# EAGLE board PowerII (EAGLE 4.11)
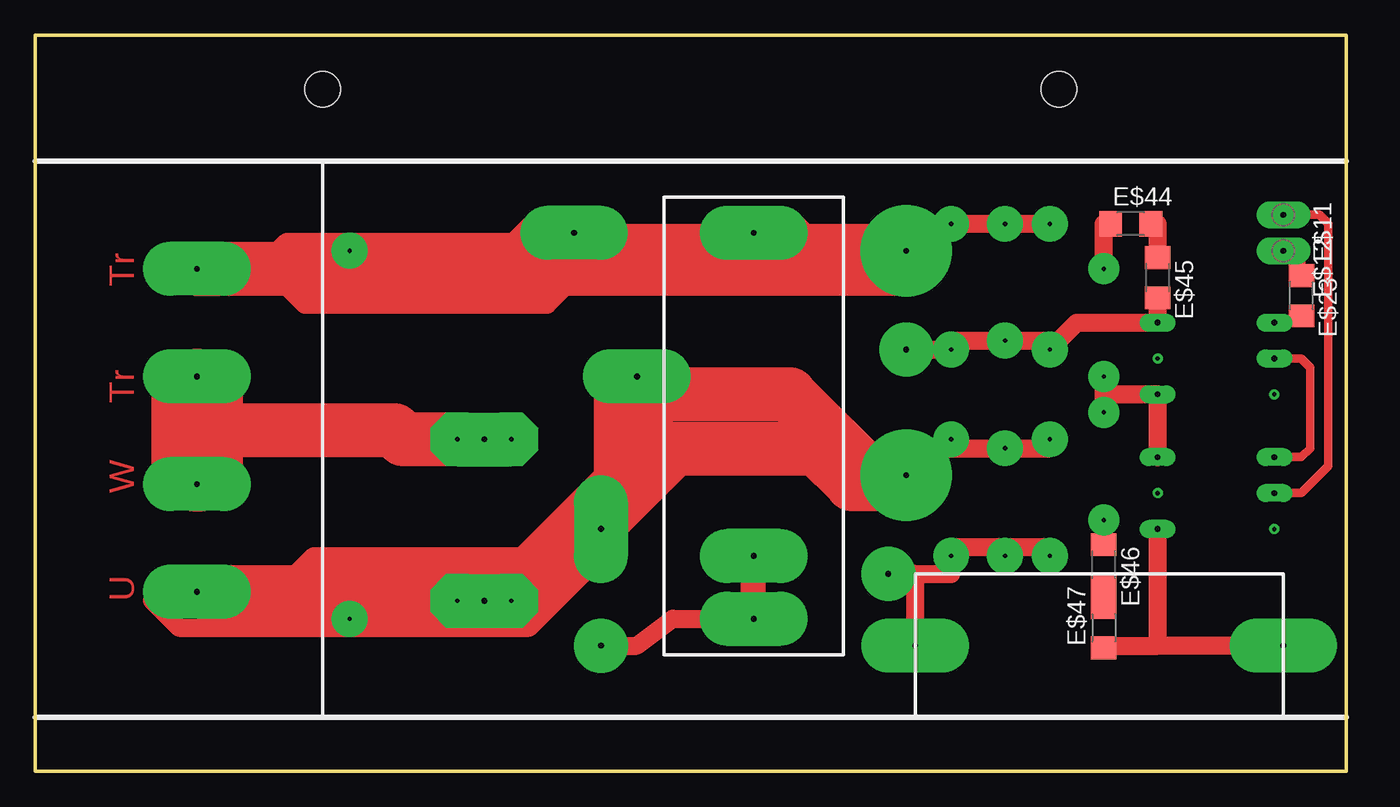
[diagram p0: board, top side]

Size 92.71 x 52.07 mm. Coordinates in mm from the lower left corner, seen from the top.
Outline: 0,0 0,52.07 92.71,52.07 92.71,0 0,0
Copper layers (1*16): Top 0.035mm / dielectric 1.5mm / Bottom 0.035mm
Design rules "default": minimum track width 10mil, minimum drill 24mil, track to track 8mil, track to pad 8mil, pad to pad 8mil, via to via 8mil, smd to smd 8mil, copper to edge 40mil, drill to drill 8mil, minimum pad ring 10mil, minimum via ring 8mil, stop-mask expansion 4mil, vias tented up to drill 0mil, thermal gap 10mil
Holes 2.54 mm at 20.32,48.26 72.39,48.26

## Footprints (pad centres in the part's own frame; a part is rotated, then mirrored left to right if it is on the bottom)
EC3,81 = drill 0.406 pad 3.81 long: P$1 0,0
EC1,27 = drill 0.406 pad 1.27 long: P$1 0,0
P1-13Y = drill 0.406 pad 1.905 long: 1 0,0
R1206 = smd 1.6 x 1.803: 1 -1.422,0; 2 1.422,0

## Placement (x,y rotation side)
E$1  [EC3,81]  11.43,35.56 90 top
E$2  [EC3,81]  31.75,23.5 270 top
E$3  [EC3,81]  11.43,27.94 90 top
E$4  [EC3,81]  11.43,20.32 90 top
E$5  [EC3,81]  11.43,12.7 90 top
E$6  [EC3,81]  50.8,10.79 270 top
E$7  [EC3,81]  38.1,38.1 270 bottom
E$8  [EC3,81]  50.8,38.1 270 top
E$9  [EC1,27]  79.38,17.14 90 top
E$10  [EC1,27]  87.63,31.75 270 top
E$11  [P1-13Y]  88.27,39.37 270 top
E$12  [P1-13Y]  88.27,36.83 270 top
E$13  [EC1,27]  87.63,29.21 270 top
E$15  [EC1,27]  79.38,26.67 270 top
E$17  [EC1,27]  79.38,31.75 270 top
E$19  [EC1,27]  79.38,22.23 90 top
E$20  [EC1,27]  87.63,22.23 90 top
E$21  [EC1,27]  87.63,19.68 90 top
E$23  [R1206]  89.53,33.66 270 top
E$24  [EC3,81]  42.55,27.94 90 top
E$37  [EC3,81]  88.27,8.89 90 top
E$38  [EC3,81]  62.23,8.89 90 top
E$39  [EC3,81]  50.8,15.24 90 top
E$42  [EC3,81]  31.75,12.06 270 top
E$44  [R1206]  77.47,38.73 0 top
E$45  [R1206]  79.38,34.92 270 top
E$46  [R1206]  75.56,14.61 270 top
E$47  [R1206]  75.56,10.16 90 top
E$48  [EC3,81]  40.01,17.14 180 top

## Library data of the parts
E$1-E$10 E$13 E$15 E$17 E$19-E$21 E$24 E$37-E$39 E$42 E$48 = Pads
E$11 E$12 = testpad
E$23 E$44-E$47 = smd-ipc

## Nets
S$2: E$5.P$1
S$4: E$1.P$1
S$8: E$13.P$1 E$20.P$1
S$9: E$15.P$1 E$19.P$1
S$12: E$11.1 E$21.P$1
S$19: E$38.P$1
S$29: E$6.P$1 E$39.P$1
S$30: E$10.P$1
S$32: E$9.P$1 E$37.P$1
S$41: E$17.P$1

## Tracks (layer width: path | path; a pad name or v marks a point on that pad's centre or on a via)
S$1
  Top 1.27: 17.78,34.29 19.05,33.02 36.2,33.02 37.47,34.29
S$2  (via drill 0.41 pad 6.45)
  Top 1.27: v61.59,20.95 61.59,21.59
  Top 3.81: E$5.P$1 33.66,12.7 40.01,19.05 | 43.81,26.67 53.34,26.67 59.69,20.32 | 59.69,20.32 v61.59,20.95 | 59.69,20.32 57.78,20.32 55.24,22.86 43.81,22.86 | 43.81,22.86 43.18,22.86 | 43.18,22.23 43.81,22.86 | 43.18,22.23 43.18,27.94 | 40.01,19.05 43.18,22.23 | 40.01,15.24 40.01,19.05
S$3
  Top 1.016: 27.94,13.34 24.77,13.34
S$4  (via drill 0.41 pad 6.45)
  Top 3.81: 46.99,35.56 61.59,35.56 | 46.99,35.56 45.72,36.83 38.1,36.83 | 37.47,36.83 38.1,36.83 | E$1.P$1 46.99,35.56 | 60.96,36.83 53.98,36.83 52.7,38.1 | 60.96,36.83 v61.59,36.83 | 38.1,36.83 60.96,36.83
S$6  (via drill 0.3 pad 0.81)
  other vias: 20.32,48.26
S$7  (via drill 0.3 pad 0.81)
  other vias: 72.39,48.26
S$8
  Top 0.61: 88.27,29.21 E$13.P$1 89.53,29.21 90.17,28.57 90.17,22.86 89.53,22.23 E$20.P$1
S$9  (via drill 0.3 pad 2.18)
  Top 1.27: E$19.P$1 E$15.P$1 75.56,26.67 | v75.56,25.4 75.56,26.67 | 75.56,26.67 v75.56,27.94
S$10  (via drill 0.41 pad 3.81)
  Top 1.27: 51.44,10.79 45.09,10.79 42.55,8.89 v40.01,8.89
S$11  (via drill 0.3 pad 2.54)
  Top 1.27: 62.87,38.73 v64.77,38.73 v68.58,38.73 v71.75,38.73
S$12
  Top 0.61: E$21.P$1 89.53,19.68 91.44,21.59 91.44,38.73 90.81,39.37 E$11.1
S$13  (via drill 0.3 pad 2.54)
  other vias: 64.77,23.5
S$14  (via drill 0.3 pad 2.54, 0.41 pad 3.81)
  Top 1.27: v61.59,29.84 v64.77,29.84
S$15  (via drill 0.3 pad 3.81)
  Top 3.81: v29.84,23.5 26.04,23.5 25.4,24.13 11.43,24.13
  Top 6.452: 11.43,21.59 11.43,24.13 11.43,26.67
S$16
  Top 1.27: 18.41,13.97 19.68,15.24 34.92,15.24
S$17
  Top 1.016: 34.92,38.73 33.02,36.83
S$18  (via drill 0.3 pad 2.18)
  Top 1.27: v75.56,17.78 75.56,16.51
S$19  (via drill 0.3 pad 2.54, 0.41 pad 3.81)
  Top 1.27: v64.77,15.24 64.77,13.97 62.23,13.97 | 62.23,13.97 v60.33,13.97 | E$38.P$1 62.23,13.97
S$20
  Top 1.016: 41.27,27.3 41.27,22.23
S$21
  Top 1.016: 40.64,27.3 40.64,20.95
S$22
  Top 1.27: 79.38,36.2 79.38,38.73
S$23  (via drill 0.3 pad 2.54)
  other vias: 71.75,23.5
S$24
  Top 1.016: 40.01,26.67 40.01,20.32
S$25  (via drill 0.3 pad 2.18)
  Top 1.27: v75.56,35.56 75.56,38.73
S$26
  Top 0.61: 89.53,34.92 89.53,36.83
S$27
  Top 1.27: 35.56,12.06 38.1,14.61
S$28
  Top 1.27: 64.77,15.88 71.75,15.88
S$29
  Top 1.778: E$6.P$1 E$39.P$1
S$30
  Top 0.61: E$10.P$1 89.53,31.75
S$31  (via drill 0.3 pad 0.61)
  other vias: 79.38,29.21
S$32
  Top 1.27: 76.2,8.89 79.38,8.89 | 79.38,8.89 E$9.P$1 | E$37.P$1 79.38,8.89
S$33  (via drill 0.3 pad 2.54)
  Top 1.27: 71.75,22.86 v68.58,22.86 64.14,22.86 61.59,20.32
S$34
  Top 1.27: 40.64,17.14 41.27,17.14 45.72,21.59
S$35  (via drill 0.3 pad 2.54)
  other vias: 68.58,15.24
S$36  (via drill 0.3 pad 2.54)
  other vias: 71.75,15.24
S$37
  Top 1.27: 16.51,36.2 17.78,37.47 35.56,37.47
S$38
  Top 1.27: 8.26,12.06 10.16,10.16 34.92,10.16 36.2,11.43 | 34.29,11.43 36.2,11.43 | 36.2,11.43 39.37,14.61
S$39
  Top 1.27: 15.88,34.29 16.51,34.29
S$40  (via drill 0.3 pad 0.61)
  other vias: 79.38,19.68
S$41  (via drill 0.3 pad 2.54)
  Top 1.27: 64.77,30.48 v68.58,30.48 71.75,30.48 v71.75,29.84 73.66,31.75 E$17.P$1 79.38,33.02
S$42  (via drill 0.3 pad 0.61)
  other vias: 87.63,26.67
S$43  (via drill 0.3 pad 0.61)
  other vias: 87.63,17.14
S$44  (via drill 0.3 pad 2.54)
  other vias: 22.23,36.83
S$45  (via drill 0.3 pad 3.81)
  other vias: 33.66,23.5
S$46  (via drill 0.3 pad 3.81)
  other vias: 29.84,12.06
S$47  (via drill 0.3 pad 3.81)
  other vias: 33.66,12.06
S$48  (via drill 0.3 pad 2.54)
  other vias: 22.23,10.79

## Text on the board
Top: Tr | Tr | W | U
